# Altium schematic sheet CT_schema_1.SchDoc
size 475 x 468 mm
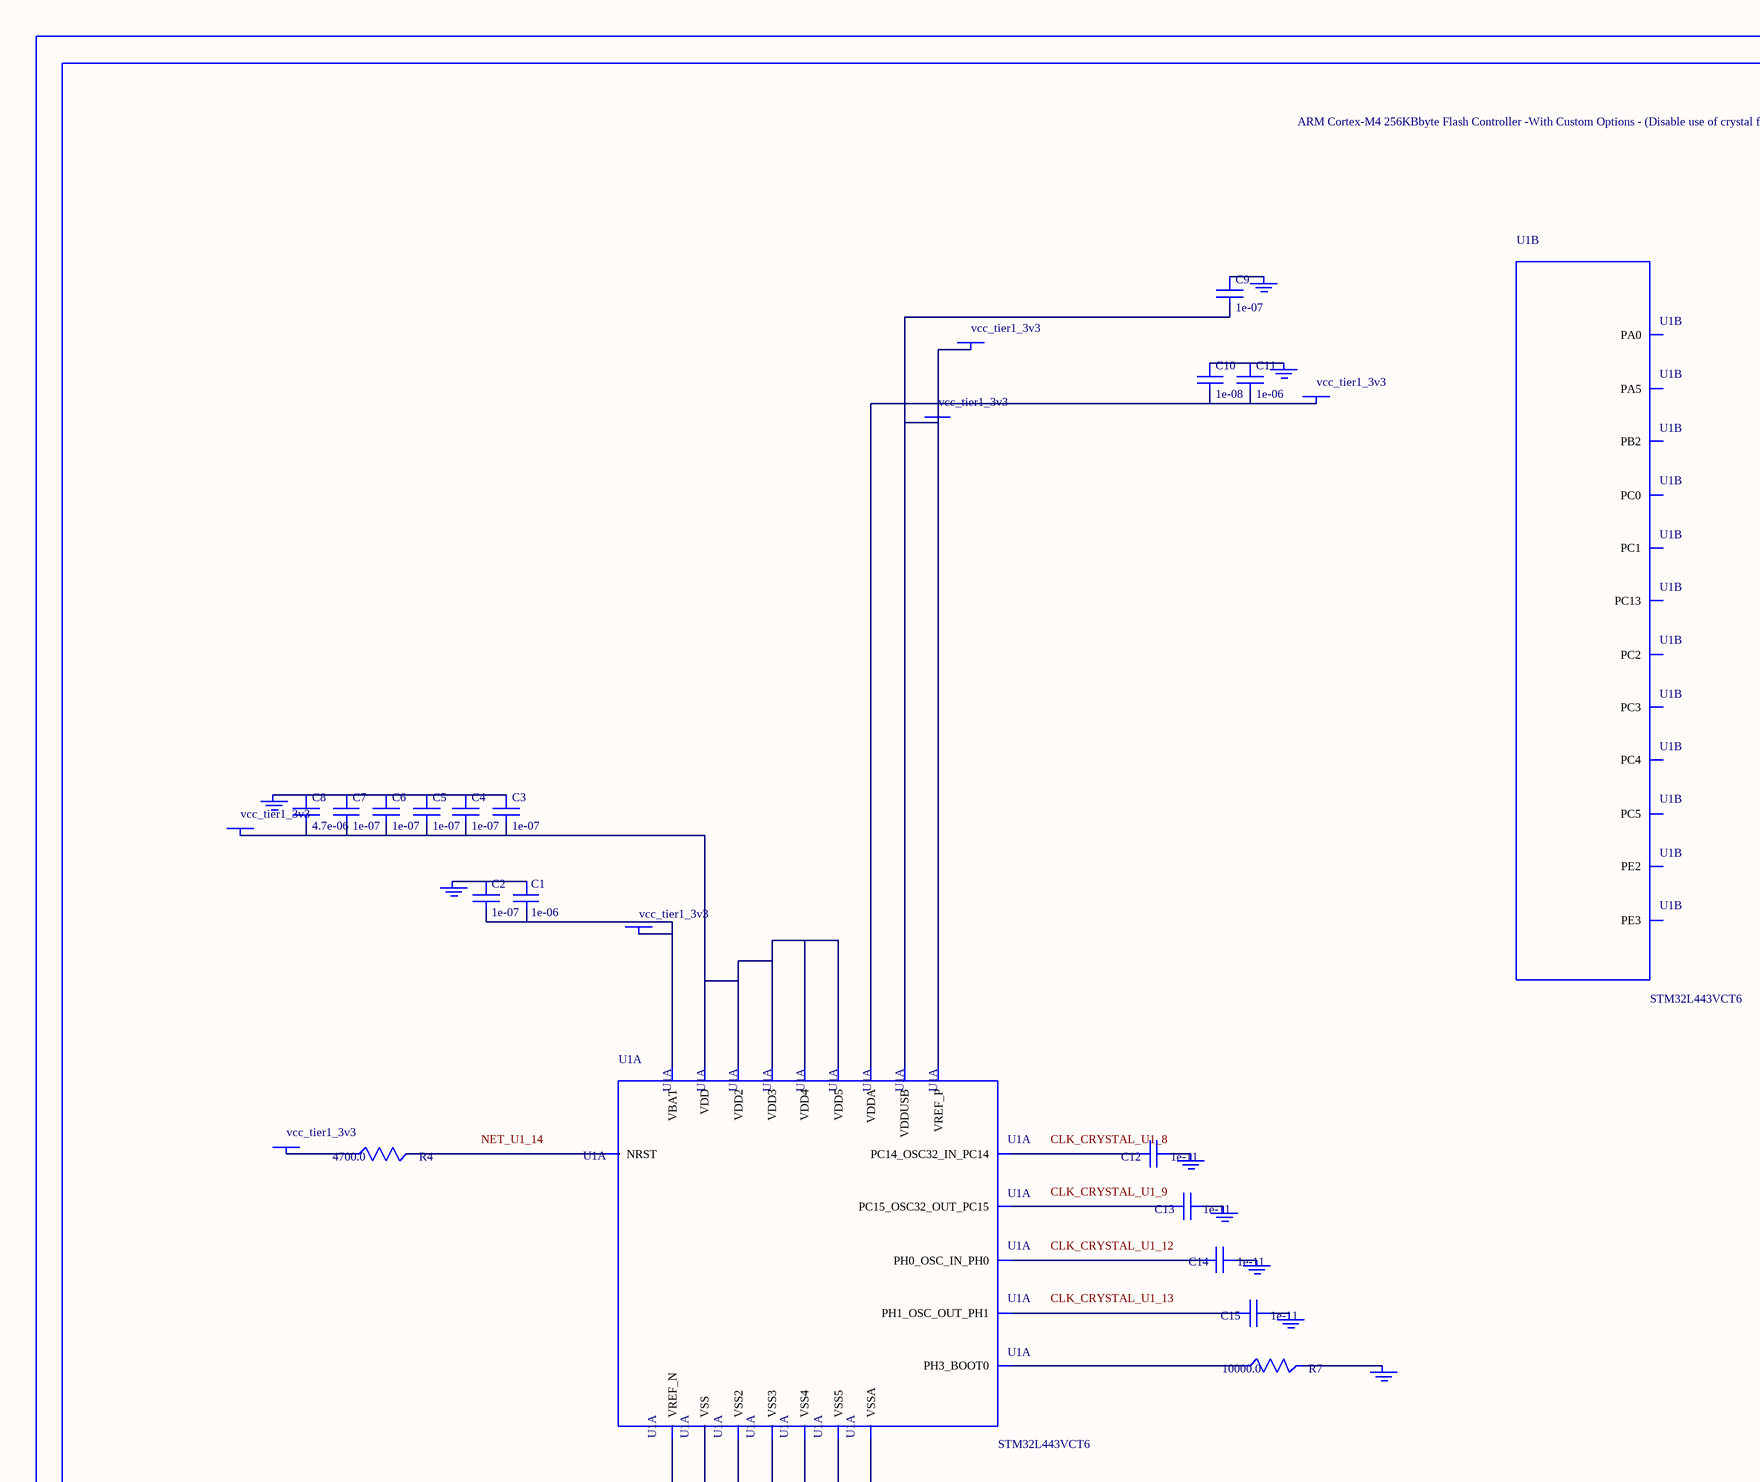
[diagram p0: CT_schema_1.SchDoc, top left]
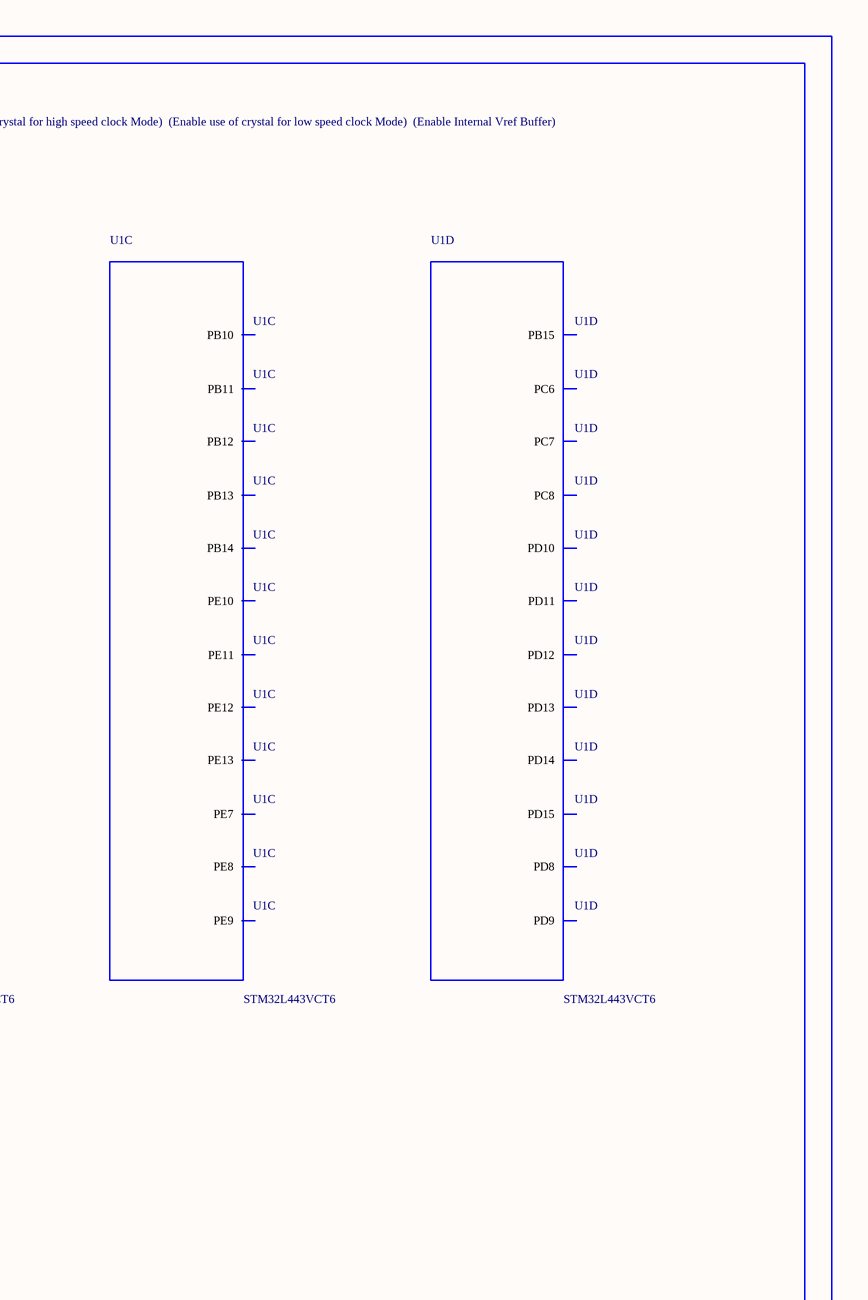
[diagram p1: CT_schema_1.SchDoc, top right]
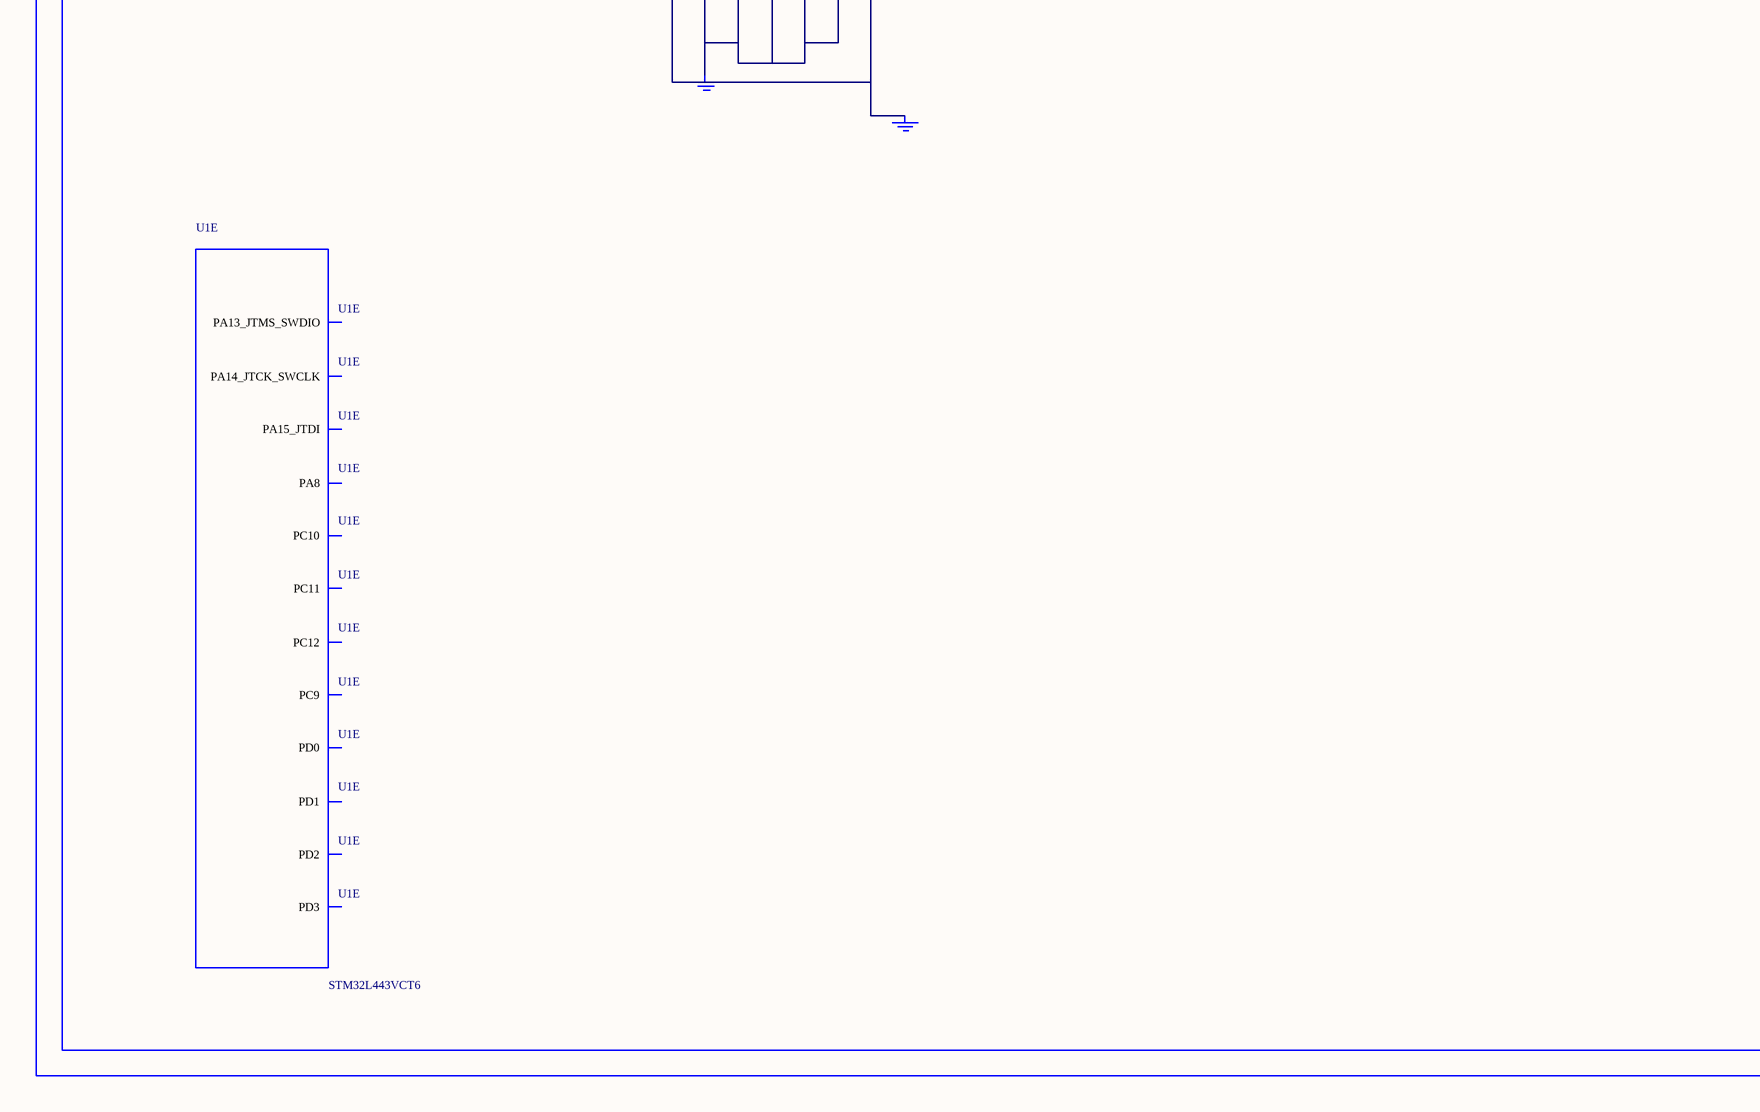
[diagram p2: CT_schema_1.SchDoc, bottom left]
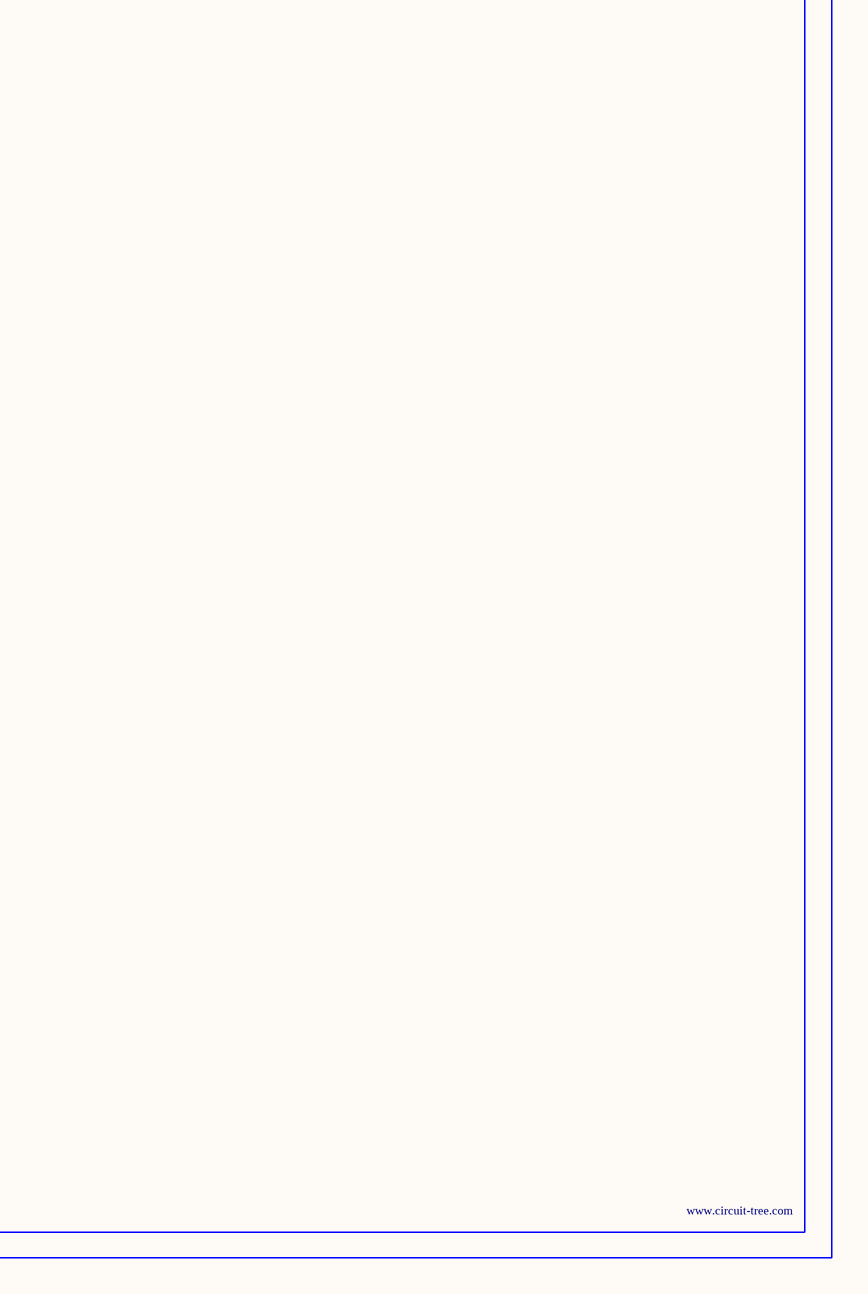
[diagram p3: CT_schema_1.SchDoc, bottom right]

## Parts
BORDER0  (no value)
C1  1e-06  [C0603]
C2  1e-07  [C0603]
C3  1e-07  [C0603]
C4  1e-07  [C0603]
C5  1e-07  [C0603]
C6  1e-07  [C0603]
C7  1e-07  [C0603]
C8  4.7e-06  [C0603]
C9  1e-07  [C0603]
C10  1e-08  [C0603]
C11  1e-06  [C0603]
C12  1e-11  [C0402]
C13  1e-11  [C0402]
C14  1e-11  [C0402]
C15  1e-11  [C0402]
GND_INSTANCE_0_0  (no value)
GND_INSTANCE_0_1  (no value)
GND_INSTANCE_0_2  (no value)
GND_INSTANCE_0_3  (no value)
GND_INSTANCE_0_4  (no value)
GND_INSTANCE_0_5  (no value)
GND_INSTANCE_0_6  (no value)
GND_INSTANCE_0_7  (no value)
GND_INSTANCE_0_8  (no value)
GND_INSTANCE_0_9  (no value)
GND_INSTANCE_0_10  (no value)
POWER_INSTANCE_0_0  vcc_tier1_3v3
POWER_INSTANCE_0_1  vcc_tier1_3v3
POWER_INSTANCE_0_2  vcc_tier1_3v3
POWER_INSTANCE_0_3  vcc_tier1_3v3
POWER_INSTANCE_0_4  vcc_tier1_3v3
POWER_INSTANCE_0_5  vcc_tier1_3v3
R4  4700.0  [R0603]
R7  10000.0  [R0603]
U1  STM32L443VCT6  [LQFP100]  (parts A,B,C,D,E of 9)

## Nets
NetC1_1: C1.1 C2.1 GND_INSTANCE_0_0.0(GND)
NetC1_2: C1.2 C2.2 POWER_INSTANCE_0_0.0(PWR) U1.6(VBAT)
NetC3_1: C3.1 C4.1 C5.1 C6.1 C7.1 C8.1 GND_INSTANCE_0_3.0(GND)
NetC3_2: C3.2 C4.2 C5.2 C6.2 C7.2 C8.2 POWER_INSTANCE_0_1.0(PWR) U1.11(VDD) U1.28(VDD2) U1.50(VDD3) U1.75(VDD4) U1.100(VDD5)
NetC9_1: C9.1 GND_INSTANCE_0_8.0(GND)
NetC9_2: C9.2 POWER_INSTANCE_0_2.0(PWR) POWER_INSTANCE_0_4.0(PWR) U1.21(VREF_P) U1.73(VDDUSB)
NetC10_1: C10.1 C11.1 GND_INSTANCE_0_7.0(GND)
NetC10_2: C10.2 C11.2 POWER_INSTANCE_0_3.0(PWR) U1.22(VDDA)
NetC12_1: C12.1 GND_INSTANCE_0_1.0(GND)
NetC12_2: C12.2 U1.8(PC14_OSC32_IN_PC14)
NetC13_1: C13.1 GND_INSTANCE_0_2.0(GND)
NetC13_2: C13.2 U1.9(PC15_OSC32_OUT_PC15)
NetC14_1: C14.1 GND_INSTANCE_0_4.0(GND)
NetC14_2: C14.2 U1.12(PH0_OSC_IN_PH0)
NetC15_1: C15.1 GND_INSTANCE_0_5.0(GND)
NetC15_2: C15.2 U1.13(PH1_OSC_OUT_PH1)
NetGND_INSTANCE_0_6_0: GND_INSTANCE_0_6.0(GND) U1.19(VSSA) U1.20(VREF_N)
NetGND_INSTANCE_0_9_0: GND_INSTANCE_0_9.0(GND) R7.2
NetGND_INSTANCE_0_10_0: GND_INSTANCE_0_10.0(GND) U1.10(VSS) U1.27(VSS2) U1.49(VSS3) U1.74(VSS4) U1.99(VSS5)
NetPOWER_INSTANCE_0_5_0: POWER_INSTANCE_0_5.0(PWR) R4.1
NetR4_2: R4.2 U1.14(NRST)
NetR7_1: R7.1 U1.94(PH3_BOOT0)

Not connected (* = marked no-connect by the designer): U1 1(PE2) 2(PE3) 7(PC13) 15(PC0) 16(PC1) 17(PC2) 18(PC3) 23(PA0) 30(PA5) 33(PC4) 34(PC5) 37(PB2) 38(PE7) 39(PE8) 40(PE9) 41(PE10) 42(PE11) 43(PE12) 44(PE13) 47(PB10) 48(PB11) 51(PB12) 52(PB13) 53(PB14) 54(PB15) 55(PD8) 56(PD9) 57(PD10) 58(PD11) 59(PD12) 60(PD13) 61(PD14) 62(PD15) 63(PC6) 64(PC7) 65(PC8) 66(PC9) 67(PA8) 72(PA13_JTMS_SWDIO) 76(PA14_JTCK_SWCLK) 77(PA15_JTDI) 78(PC10) 79(PC11) 80(PC12) 81(PD0) 82(PD1) 83(PD2) 84(PD3)

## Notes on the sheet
- Labels drawn without touching a wire or pin: CLK_CRYSTAL_U1_8, CLK_CRYSTAL_U1_9, CLK_CRYSTAL_U1_12, CLK_CRYSTAL_U1_13, NET_U1_14

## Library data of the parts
BORDER0 = BORDER_PAGE0
C1 C11 = C0603C105K3RACTU
C2-C7 C9 = 06035C104K4Z2A
C8 = GRM188R6YA475KE15D
C10 = 06035C103K4Z2A
C12-C15 = C0402C100K3GACTU
GND_INSTANCE_0_0-GND_INSTANCE_0_10 = GND
POWER_INSTANCE_0_0-POWER_INSTANCE_0_5 = PWR
R4 = RC0603JR-074K7L
R7 = RC0603JR-0710KL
